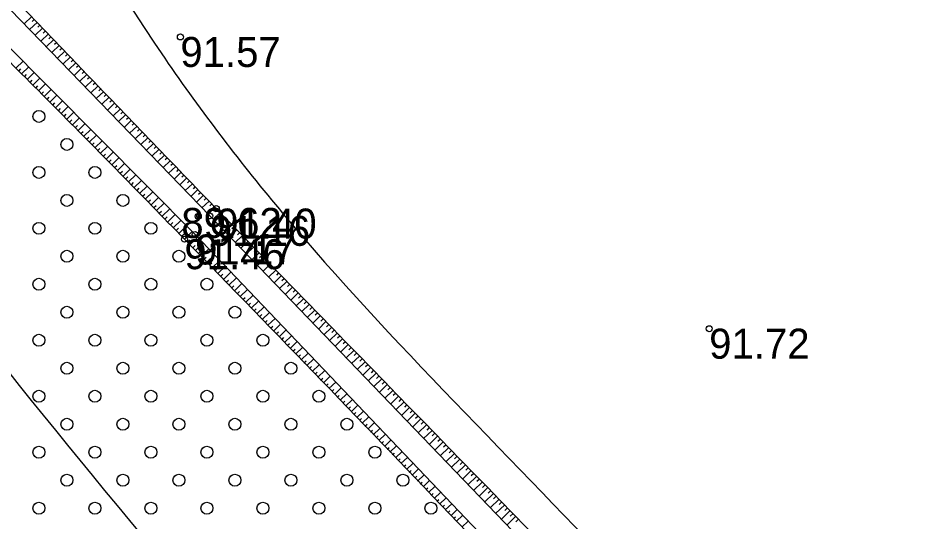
# Model space of a CAD drawing. Extents: x 316000 to 728450, y 314368 to 726000.
# Drawn here: x 726103.9 to 726217, y 315190.8 to 315253.8 of the extents above; entities that cross this region are included whole.
import ezdxf

# ---------------------------------------------------------------- set-up
doc = ezdxf.new("R2010")
doc.units = 0
for name, color, linetype in [('HIDG_ELEM_####_####_#', 7, 'Continuous'), ('HIDG_GRAV_####_####_#', 7, 'Continuous'), ('RELJ_AATZ_####_TKST_#', 7, 'Continuous'), ('RELJ_ELEM_####_####_#', 7, 'Continuous'), ('RELJ_HORZ_PAMT_####_#', 7, 'Continuous'), ('RELJ_NOGA_####_####_#', 7, 'Continuous'), ('TERT_ELEM_####_####_#', 7, 'Continuous')]:
    doc.layers.add(name, color=color, linetype=linetype)

msp = doc.modelspace()

# ---------------------------------------------------------------- linework, layer by layer
at = {"layer": 'HIDG_ELEM_####_####_#'}
msp.add_circle((726126.42, 315229.01), 0.225, dxfattribs=at)
at = {"layer": 'HIDG_GRAV_####_####_#'}
for points in [[(726259.18, 315086.52), (726260.77, 315088.86), (726179.01, 315175.77), (726127.86, 315229.06), (726063.06, 315296.07), (725998.34, 315364.32), (725936.65, 315430.32), (725875.35, 315494.08), (725809.44, 315562.19), (725743.94, 315631.87)], [(725741.16, 315628.11), (725806.06, 315558.99), (725870.9, 315491.87), (725934.12, 315427.08), (725995.78, 315361.63), (726059.85, 315293.4), (726126.03, 315226.73), (726194.49, 315154.86), (726259.18, 315086.52)]]:
    msp.add_lwpolyline(points, dxfattribs=at)
at = {"layer": 'RELJ_ELEM_####_####_#'}
for centre in [(726124.18, 315251.43), (726128.67, 315229.97), (726126.42, 315229.01), (726127.86, 315229.06), (726126.03, 315226.73), (726124.69, 315226.14), (726190.28, 315214.95)]:
    msp.add_circle(centre, 0.375, dxfattribs=at)
at = {"layer": 'RELJ_HORZ_PAMT_####_#'}
for points in [[(726116.34, 315699.09), (726105.94, 315702.69), (726040.13, 315715), (725990.82, 315710.42), (725942.03, 315708.25), (725920.28, 315706.77), (725880.37, 315714.51), (725859.05, 315708.68), (725859.05, 315672.66), (725851.26, 315613.97), (725853.47, 315568.9), (725841, 315555.79), (725885.56, 315509.63), (725935.94, 315461.49), (725983.42, 315406.25), (726032.86, 315360.51), (726082.85, 315311.19), (726122.23, 315248.76), (726137.05, 315229.29), (726180.19, 315183.1), (726194.52, 315168.27), (726211.91, 315146.93), (726212.51, 315143.16)], [(726208.53, 315137.52), (726189.05, 315133.53), (726141.5, 315164), (726090.79, 315224.6)]]:
    msp.add_spline(points, degree=3, dxfattribs=at)
at = {"layer": 'RELJ_NOGA_####_####_#'}
for p, q in [((726105.61, 315254.01), (726104.64, 315253.07)), ((726106.31, 315253.29), (726105.33, 315252.35)), ((726105.96, 315253.65), (726105.67, 315253.37)), ((726106.65, 315252.93), (726106.36, 315252.65)), ((726107, 315252.56), (726106.03, 315251.64)), ((726107.69, 315251.84), (726106.72, 315250.92)), ((726107.34, 315252.2), (726107.05, 315251.92)), ((726108.38, 315251.12), (726107.42, 315250.2)), ((726108.03, 315251.48), (726107.74, 315251.2)), ((726109.07, 315250.4), (726108.11, 315249.48)), ((726108.73, 315250.76), (726108.44, 315250.48)), ((726109.76, 315249.67), (726108.81, 315248.76)), ((726109.42, 315250.04), (726109.13, 315249.76)), ((726110.11, 315249.31), (726109.82, 315249.04)), ((726103.63, 315247.51), (726104.52, 315248.4)), ((726110.45, 315248.95), (726109.5, 315248.04)), ((726111.15, 315248.23), (726110.2, 315247.32)), ((726110.8, 315248.59), (726110.51, 315248.32)), ((726103.98, 315247.16), (726104.25, 315247.43)), ((726104.34, 315246.81), (726105.22, 315247.69)), ((726105.04, 315246.1), (726105.92, 315246.98)), ((726111.84, 315247.51), (726110.89, 315246.6)), ((726111.49, 315247.87), (726111.21, 315247.6)), ((726112.18, 315247.15), (726111.9, 315246.88)), ((726104.69, 315246.45), (726104.96, 315246.72)), ((726105.4, 315245.75), (726105.66, 315246.01)), ((726105.75, 315245.39), (726106.63, 315246.27)), ((726112.53, 315246.79), (726111.59, 315245.88)), ((726113.22, 315246.06), (726112.28, 315245.16)), ((726112.88, 315246.42), (726112.59, 315246.15)), ((726106.11, 315245.04), (726106.37, 315245.3)), ((726106.46, 315244.69), (726107.33, 315245.56)), ((726107.17, 315243.98), (726108.04, 315244.85)), ((726113.91, 315245.34), (726112.98, 315244.45)), ((726113.57, 315245.7), (726113.29, 315245.43)), ((726114.26, 315244.98), (726113.98, 315244.71)), ((726106.81, 315244.33), (726107.07, 315244.59)), ((726107.52, 315243.62), (726107.78, 315243.89)), ((726107.87, 315243.27), (726108.74, 315244.14)), ((726114.6, 315244.62), (726113.67, 315243.73)), ((726115.3, 315243.9), (726114.37, 315243.01)), ((726114.95, 315244.26), (726114.67, 315243.99)), ((726108.23, 315242.92), (726108.49, 315243.18)), ((726108.58, 315242.56), (726109.45, 315243.43)), ((726108.93, 315242.21), (726109.19, 315242.47)), ((726109.29, 315241.85), (726110.15, 315242.72)), ((726115.99, 315243.18), (726115.06, 315242.29)), ((726115.64, 315243.54), (726115.36, 315243.27)), ((726116.68, 315242.45), (726115.76, 315241.57)), ((726116.33, 315242.81), (726116.06, 315242.55)), ((726109.64, 315241.5), (726109.9, 315241.76)), ((726109.99, 315241.15), (726110.86, 315242.01)), ((726117.37, 315241.73), (726116.45, 315240.85)), ((726117.03, 315242.09), (726116.75, 315241.83)), ((726117.72, 315241.37), (726117.44, 315241.11)), ((726110.34, 315240.79), (726110.6, 315241.05)), ((726110.7, 315240.44), (726111.56, 315241.3)), ((726111.05, 315240.08), (726111.31, 315240.34)), ((726111.4, 315239.73), (726112.27, 315240.59)), ((726118.07, 315241.01), (726117.15, 315240.13)), ((726118.76, 315240.29), (726117.84, 315239.41)), ((726118.41, 315240.65), (726118.14, 315240.39)), ((726111.75, 315239.37), (726112.01, 315239.63)), ((726112.1, 315239.02), (726112.97, 315239.88)), ((726112.81, 315238.3), (726113.68, 315239.17)), ((726119.45, 315239.57), (726118.54, 315238.69)), ((726119.1, 315239.93), (726118.83, 315239.67)), ((726119.8, 315239.21), (726119.52, 315238.94)), ((726112.45, 315238.66), (726112.72, 315238.92)), ((726113.16, 315237.95), (726113.42, 315238.21)), ((726113.51, 315237.59), (726114.39, 315238.46)), ((726120.14, 315238.85), (726119.23, 315237.97)), ((726120.84, 315238.12), (726119.93, 315237.26)), ((726120.49, 315238.49), (726120.22, 315238.22)), ((726113.86, 315237.24), (726114.12, 315237.5)), ((726114.21, 315236.88), (726115.09, 315237.75)), ((726114.91, 315236.17), (726115.8, 315237.04)), ((726121.53, 315237.4), (726120.63, 315236.54)), ((726121.18, 315237.76), (726120.91, 315237.5)), ((726121.87, 315237.04), (726121.6, 315236.78)), ((726114.56, 315236.52), (726114.83, 315236.79)), ((726115.26, 315235.81), (726115.53, 315236.07)), ((726115.61, 315235.46), (726116.5, 315236.33)), ((726122.22, 315236.68), (726121.32, 315235.82)), ((726122.91, 315235.96), (726122.02, 315235.1)), ((726122.57, 315236.32), (726122.3, 315236.06)), ((726115.96, 315235.1), (726116.23, 315235.36)), ((726116.31, 315234.74), (726117.21, 315235.62)), ((726116.66, 315234.38), (726116.93, 315234.65)), ((726117.01, 315234.03), (726117.91, 315234.91)), ((726123.61, 315235.24), (726122.71, 315234.38)), ((726123.26, 315235.6), (726122.99, 315235.34)), ((726123.95, 315234.88), (726123.68, 315234.62)), ((726117.36, 315233.67), (726117.63, 315233.93)), ((726117.71, 315233.31), (726118.62, 315234.2)), ((726118.41, 315232.6), (726119.32, 315233.49)), ((726124.3, 315234.52), (726123.41, 315233.66)), ((726124.99, 315233.8), (726124.1, 315232.94)), ((726124.65, 315234.16), (726124.38, 315233.9)), ((726125.34, 315233.44), (726125.07, 315233.18)), ((726118.06, 315232.96), (726118.34, 315233.22)), ((726118.76, 315232.24), (726119.04, 315232.51)), ((726119.11, 315231.88), (726120.03, 315232.78)), ((726125.68, 315233.08), (726124.8, 315232.22)), ((726126.38, 315232.36), (726125.49, 315231.5)), ((726126.03, 315232.72), (726125.77, 315232.46)), ((726119.46, 315231.53), (726119.74, 315231.79)), ((726119.81, 315231.17), (726120.73, 315232.07)), ((726120.51, 315230.45), (726121.44, 315231.36)), ((726127.07, 315231.63), (726126.19, 315230.78)), ((726126.72, 315232), (726126.46, 315231.74)), ((726127.42, 315231.27), (726127.15, 315231.02)), ((726120.16, 315230.81), (726120.44, 315231.08)), ((726120.86, 315230.09), (726121.14, 315230.37)), ((726121.21, 315229.74), (726122.14, 315230.65)), ((726127.76, 315230.91), (726126.88, 315230.07)), ((726128.46, 315230.19), (726127.58, 315229.35)), ((726128.11, 315230.55), (726127.85, 315230.3)), ((726121.55, 315229.38), (726121.84, 315229.65)), ((726121.9, 315229.02), (726122.85, 315229.93)), ((726122.25, 315228.66), (726122.54, 315228.94)), ((726122.6, 315228.3), (726123.55, 315229.22)), ((726129.15, 315229.47), (726128.27, 315228.63)), ((726128.8, 315229.83), (726128.54, 315229.58)), ((726129.5, 315229.11), (726129.23, 315228.86)), ((726122.95, 315227.94), (726123.24, 315228.22)), ((726123.3, 315227.58), (726124.26, 315228.51)), ((726123.99, 315226.87), (726124.96, 315227.8)), ((726129.84, 315228.75), (726128.96, 315227.9)), ((726130.54, 315228.03), (726129.66, 315227.18)), ((726130.19, 315228.39), (726129.93, 315228.14)), ((726123.65, 315227.22), (726123.93, 315227.51)), ((726124.34, 315226.51), (726124.63, 315226.79)), ((726124.69, 315226.15), (726125.67, 315227.09)), ((726131.23, 315227.31), (726130.35, 315226.46)), ((726130.89, 315227.67), (726130.62, 315227.42)), ((726131.58, 315226.95), (726131.31, 315226.7)), ((726125.04, 315225.79), (726125.33, 315226.07)), ((726125.38, 315225.43), (726126.36, 315226.38)), ((726126.08, 315224.71), (726127.05, 315225.65)), ((726131.93, 315226.59), (726131.04, 315225.74)), ((726132.62, 315225.87), (726131.74, 315225.02)), ((726132.27, 315226.23), (726132.01, 315225.98)), ((726132.97, 315225.51), (726132.7, 315225.26)), ((726125.73, 315225.07), (726126.03, 315225.35)), ((726126.43, 315224.35), (726126.72, 315224.63)), ((726126.78, 315223.99), (726127.74, 315224.93)), ((726133.32, 315225.15), (726132.43, 315224.3)), ((726134.01, 315224.44), (726133.12, 315223.57)), ((726133.66, 315224.8), (726133.4, 315224.54)), ((726127.12, 315223.63), (726127.41, 315223.91)), ((726127.47, 315223.27), (726128.43, 315224.2)), ((726128.17, 315222.56), (726129.12, 315223.48)), ((726134.71, 315223.72), (726133.81, 315222.85)), ((726134.36, 315224.08), (726134.09, 315223.82)), ((726135.05, 315223.36), (726134.79, 315223.1)), ((726127.82, 315222.92), (726128.11, 315223.19)), ((726128.52, 315222.2), (726128.8, 315222.47)), ((726128.86, 315221.84), (726129.81, 315222.76)), ((726135.4, 315223), (726134.51, 315222.13)), ((726136.1, 315222.28), (726135.2, 315221.41)), ((726135.75, 315222.64), (726135.48, 315222.38)), ((726129.21, 315221.48), (726129.49, 315221.75)), ((726129.56, 315221.12), (726130.5, 315222.03)), ((726129.91, 315220.76), (726130.19, 315221.03)), ((726130.25, 315220.4), (726131.19, 315221.31)), ((726136.79, 315221.56), (726135.89, 315220.69)), ((726136.45, 315221.92), (726136.18, 315221.66)), ((726137.14, 315221.2), (726136.87, 315220.94)), ((726130.6, 315220.04), (726130.88, 315220.31)), ((726130.95, 315219.68), (726131.88, 315220.58)), ((726131.64, 315218.96), (726132.57, 315219.86)), ((726137.49, 315220.84), (726136.58, 315219.96)), ((726138.19, 315220.13), (726137.28, 315219.24)), ((726137.84, 315220.49), (726137.57, 315220.22)), ((726131.3, 315219.32), (726131.58, 315219.59)), ((726131.99, 315218.6), (726132.27, 315218.87)), ((726132.34, 315218.24), (726133.26, 315219.14)), ((726138.88, 315219.41), (726137.97, 315218.52)), ((726138.54, 315219.77), (726138.26, 315219.5)), ((726139.23, 315219.05), (726138.96, 315218.78)), ((726132.69, 315217.88), (726132.96, 315218.15)), ((726133.03, 315217.52), (726133.95, 315218.41)), ((726133.73, 315216.8), (726134.64, 315217.69)), ((726139.58, 315218.69), (726138.66, 315217.8)), ((726140.28, 315217.98), (726139.35, 315217.08)), ((726139.93, 315218.33), (726139.65, 315218.07)), ((726140.63, 315217.62), (726140.35, 315217.35)), ((726133.38, 315217.16), (726133.66, 315217.43)), ((726134.08, 315216.44), (726134.35, 315216.71)), ((726134.42, 315216.09), (726135.33, 315216.96)), ((726140.97, 315217.26), (726140.05, 315216.36)), ((726141.67, 315216.54), (726140.74, 315215.63)), ((726141.32, 315216.9), (726141.04, 315216.63)), ((726134.77, 315215.73), (726135.04, 315215.99)), ((726135.12, 315215.37), (726136.02, 315216.24)), ((726135.81, 315214.65), (726136.71, 315215.51)), ((726142.37, 315215.83), (726141.43, 315214.91)), ((726142.02, 315216.18), (726141.74, 315215.91)), ((726142.72, 315215.47), (726142.44, 315215.19)), ((726135.46, 315215.01), (726135.74, 315215.27)), ((726136.16, 315214.29), (726136.43, 315214.55)), ((726136.51, 315213.93), (726137.4, 315214.79)), ((726143.07, 315215.11), (726142.13, 315214.19)), ((726143.77, 315214.39), (726142.82, 315213.47)), ((726143.42, 315214.75), (726143.13, 315214.47)), ((726136.85, 315213.57), (726137.12, 315213.83)), ((726137.2, 315213.21), (726138.09, 315214.07)), ((726137.55, 315212.85), (726137.81, 315213.1)), ((726137.89, 315212.49), (726138.78, 315213.34)), ((726144.46, 315213.68), (726143.51, 315212.75)), ((726144.11, 315214.03), (726143.83, 315213.76)), ((726144.81, 315213.32), (726144.53, 315213.04)), ((726138.24, 315212.13), (726138.51, 315212.38)), ((726138.59, 315211.77), (726139.47, 315212.62)), ((726145.16, 315212.96), (726144.2, 315212.03)), ((726145.86, 315212.24), (726144.9, 315211.3)), ((726145.51, 315212.6), (726145.22, 315212.32)), ((726138.94, 315211.41), (726139.2, 315211.66)), ((726139.28, 315211.05), (726140.16, 315211.89)), ((726139.63, 315210.69), (726139.89, 315210.94)), ((726139.98, 315210.33), (726140.85, 315211.17)), ((726146.56, 315211.53), (726145.59, 315210.58)), ((726146.21, 315211.89), (726145.92, 315211.6)), ((726147.26, 315210.81), (726146.28, 315209.86)), ((726146.91, 315211.17), (726146.61, 315210.89)), ((726140.32, 315209.97), (726140.59, 315210.22)), ((726140.67, 315209.61), (726141.54, 315210.45)), ((726141.36, 315208.89), (726142.23, 315209.72)), ((726147.95, 315210.1), (726146.97, 315209.14)), ((726147.6, 315210.45), (726147.31, 315210.17)), ((726148.3, 315209.74), (726148.01, 315209.45)), ((726141.02, 315209.25), (726141.28, 315209.5)), ((726141.71, 315208.53), (726141.97, 315208.78)), ((726142.06, 315208.17), (726142.92, 315209)), ((726148.65, 315209.38), (726147.67, 315208.42)), ((726149.35, 315208.67), (726148.36, 315207.7)), ((726149, 315209.02), (726148.7, 315208.73)), ((726142.4, 315207.81), (726142.66, 315208.05)), ((726142.75, 315207.45), (726143.61, 315208.27)), ((726143.44, 315206.72), (726144.3, 315207.55)), ((726150.05, 315207.95), (726149.05, 315206.98)), ((726149.7, 315208.31), (726149.4, 315208.02)), ((726150.4, 315207.59), (726150.1, 315207.3)), ((726143.1, 315207.09), (726143.35, 315207.33)), ((726143.79, 315206.36), (726144.05, 315206.61)), ((726144.14, 315206), (726144.99, 315206.82)), ((726150.75, 315207.23), (726149.74, 315206.25)), ((726151.45, 315206.52), (726150.44, 315205.53)), ((726151.1, 315206.88), (726150.79, 315206.58)), ((726144.48, 315205.64), (726144.74, 315205.89)), ((726144.83, 315205.28), (726145.68, 315206.1)), ((726145.18, 315204.92), (726145.43, 315205.17)), ((726145.52, 315204.56), (726146.37, 315205.38)), ((726152.15, 315205.8), (726151.13, 315204.81)), ((726151.8, 315206.16), (726151.49, 315205.86)), ((726152.49, 315205.45), (726152.19, 315205.15)), ((726145.87, 315204.2), (726146.12, 315204.45)), ((726146.22, 315203.84), (726147.06, 315204.65)), ((726152.84, 315205.09), (726151.82, 315204.09)), ((726153.54, 315204.37), (726152.51, 315203.37)), ((726153.19, 315204.73), (726152.89, 315204.43)), ((726153.89, 315204.01), (726153.58, 315203.71)), ((726146.56, 315203.48), (726146.82, 315203.72)), ((726146.91, 315203.12), (726147.75, 315203.93)), ((726147.25, 315202.76), (726147.51, 315203)), ((726147.6, 315202.4), (726148.44, 315203.2)), ((726154.24, 315203.66), (726153.21, 315202.65)), ((726154.94, 315202.94), (726153.9, 315201.92)), ((726154.59, 315203.3), (726154.28, 315203)), ((726147.95, 315202.04), (726148.2, 315202.28)), ((726148.29, 315201.68), (726149.13, 315202.48)), ((726148.99, 315200.95), (726149.82, 315201.75)), ((726155.64, 315202.23), (726154.59, 315201.2)), ((726155.29, 315202.58), (726154.98, 315202.28)), ((726155.99, 315201.87), (726155.67, 315201.56)), ((726148.64, 315201.32), (726148.89, 315201.56)), ((726149.33, 315200.59), (726149.58, 315200.83)), ((726149.68, 315200.23), (726150.51, 315201.03)), ((726156.34, 315201.51), (726155.28, 315200.48)), ((726157.04, 315200.8), (726155.98, 315199.76)), ((726156.69, 315201.15), (726156.37, 315200.84)), ((726150.02, 315199.87), (726150.27, 315200.11)), ((726150.37, 315199.51), (726151.2, 315200.31)), ((726151.06, 315198.79), (726151.89, 315199.58)), ((726157.73, 315200.08), (726156.67, 315199.04)), ((726157.39, 315200.44), (726157.07, 315200.13)), ((726158.08, 315199.72), (726157.76, 315199.41)), ((726150.72, 315199.15), (726150.96, 315199.39)), ((726151.41, 315198.43), (726151.66, 315198.67)), ((726151.75, 315198.07), (726152.58, 315198.86)), ((726158.43, 315199.36), (726157.36, 315198.32)), ((726159.13, 315198.65), (726158.05, 315197.6)), ((726158.78, 315199.01), (726158.46, 315198.69)), ((726152.1, 315197.71), (726152.35, 315197.94)), ((726152.44, 315197.34), (726153.27, 315198.13)), ((726152.79, 315196.98), (726153.04, 315197.22)), ((726153.14, 315196.62), (726153.96, 315197.41)), ((726159.83, 315197.93), (726158.75, 315196.87)), ((726159.48, 315198.29), (726159.16, 315197.97)), ((726160.53, 315197.22), (726159.44, 315196.15)), ((726160.18, 315197.58), (726159.85, 315197.26)), ((726153.48, 315196.26), (726153.73, 315196.5)), ((726153.83, 315195.9), (726154.65, 315196.68)), ((726161.23, 315196.5), (726160.13, 315195.43)), ((726160.88, 315196.86), (726160.55, 315196.54)), ((726161.58, 315196.14), (726161.25, 315195.82)), ((726154.17, 315195.54), (726154.42, 315195.77)), ((726154.52, 315195.18), (726155.34, 315195.96)), ((726154.86, 315194.82), (726155.11, 315195.05)), ((726155.21, 315194.45), (726156.03, 315195.24)), ((726161.93, 315195.79), (726160.82, 315194.71)), ((726162.62, 315195.07), (726161.51, 315193.99)), ((726162.27, 315195.43), (726161.94, 315195.1)), ((726155.55, 315194.09), (726155.8, 315194.33)), ((726155.9, 315193.73), (726156.72, 315194.51)), ((726163.32, 315194.35), (726162.21, 315193.27)), ((726162.97, 315194.71), (726162.64, 315194.39)), ((726163.67, 315194), (726163.34, 315193.67)), ((726156.25, 315193.37), (726156.49, 315193.6)), ((726156.59, 315193.01), (726157.41, 315193.79)), ((726156.94, 315192.65), (726157.18, 315192.88)), ((726157.28, 315192.28), (726158.1, 315193.06)), ((726164.02, 315193.64), (726162.9, 315192.55)), ((726164.72, 315192.92), (726163.59, 315191.83)), ((726164.37, 315193.28), (726164.03, 315192.95)), ((726157.63, 315191.92), (726157.87, 315192.16)), ((726157.97, 315191.56), (726158.79, 315192.34)), ((726158.66, 315190.84), (726159.48, 315191.62)), ((726165.42, 315192.21), (726164.28, 315191.1)), ((726165.07, 315192.56), (726164.73, 315192.23)), ((726165.77, 315191.85), (726165.42, 315191.52)), ((726158.32, 315191.2), (726158.56, 315191.43)), ((726159.35, 315190.11), (726160.17, 315190.89)), ((726166.11, 315191.49), (726164.98, 315190.38)), ((726166.46, 315191.13), (726166.12, 315190.8))]:
    msp.add_line(p, q, dxfattribs=at)
for points in [[(726259.12, 315084.51), (726262.72, 315089.26), (726261.56, 315090.84), (726260.2, 315092.42), (726257.29, 315095.53), (726218.91, 315136.38), (726180.31, 315176.84), (726128.67, 315229.97), (726063.7, 315298.11), (725999.9, 315366.09), (725937.21, 315432.09), (725876.35, 315495.23), (725810.58, 315563.08), (725744.7, 315632.91)], [(725740.86, 315626.98), (725805.54, 315558.12), (725870.39, 315491.15), (725932.8, 315426.8), (725994.98, 315360.84), (726059.66, 315292.12), (726075.75, 315275.46), (726092.08, 315259.04), (726108.47, 315242.67), (726124.69, 315226.14), (726193.27, 315154.03), (726250.06, 315092.6), (726256.32, 315085.83), (726258.82, 315084.29), (726259.12, 315084.51)]]:
    msp.add_spline(points, degree=3, dxfattribs=at)
at = {"layer": 'TERT_ELEM_####_####_#'}
for centre in [(726106.5, 315241.5), (726110, 315238), (726106.5, 315234.5), (726113.5, 315234.5), (726110, 315231), (726117, 315231), (726106.5, 315227.5), (726113.5, 315227.5), (726120.5, 315227.5), (726110, 315224), (726117, 315224), (726124, 315224), (726106.5, 315220.5), (726113.5, 315220.5), (726120.5, 315220.5), (726127.5, 315220.5), (726110, 315217), (726117, 315217), (726124, 315217), (726131, 315217), (726106.5, 315213.5), (726113.5, 315213.5), (726120.5, 315213.5), (726127.5, 315213.5), (726134.5, 315213.5), (726110, 315210), (726117, 315210), (726124, 315210), (726131, 315210), (726138, 315210), (726106.5, 315206.5), (726113.5, 315206.5), (726120.5, 315206.5), (726127.5, 315206.5), (726134.5, 315206.5), (726141.5, 315206.5), (726110, 315203), (726117, 315203), (726124, 315203), (726131, 315203), (726138, 315203), (726145, 315203), (726106.5, 315199.5), (726113.5, 315199.5), (726120.5, 315199.5), (726127.5, 315199.5), (726134.5, 315199.5), (726141.5, 315199.5), (726148.5, 315199.5), (726110, 315196), (726117, 315196), (726124, 315196), (726131, 315196), (726138, 315196), (726145, 315196), (726152, 315196), (726106.5, 315192.5), (726113.5, 315192.5), (726120.5, 315192.5), (726127.5, 315192.5), (726134.5, 315192.5), (726141.5, 315192.5), (726148.5, 315192.5), (726155.5, 315192.5)]:
    msp.add_circle(centre, 0.75, dxfattribs=at)

# ---------------------------------------------------------------- texts
at = {"layer": 'RELJ_AATZ_####_TKST_#'}
for s, p in [('91.57', (726124.18, 315247.68)), ('89.62', (726124.3, 315226.3)), ('91.40', (726128.67, 315226.22)), ('91.16', (726127.86, 315225.31)), ('91.17', (726126.03, 315222.98)), ('91.46', (726124.69, 315222.39)), ('91.72', (726190.28, 315211.2))]:
    msp.add_text(s, height=3.75, dxfattribs=at).set_placement(p)

doc.saveas('drawing.dxf')
